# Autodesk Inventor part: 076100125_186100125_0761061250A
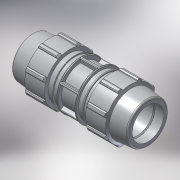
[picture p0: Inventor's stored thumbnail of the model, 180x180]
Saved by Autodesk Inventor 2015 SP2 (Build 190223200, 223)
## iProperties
Created: 2017-02
Part Number: 076100125_186100125_0761061250A
Material: PVC-Piping
Description: PLASSON REPAIR COUPLER 125
Document SubType Name: Modeling
Designer: KIM
Mass: 8658.36 g
Surface Area: 5623.3 cm^2
Volume: 6184.54 cm^3
Density: 1.4 g/cm^3
Appearance: Smooth - White
Author: KIM
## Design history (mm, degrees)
derived "07610.ipt"
feature "Solid1::07610.ipt"
tag "TaggingFeature1"
body "Solid1"
other parameters: "d2" = 125, "d4" = 38.33333, "d5" = 65.71429, "d7" = 212, "d8" = 159, "d9" = 65.71429, "d11" = 3.48571, "d12" = 169.6, "d13" = 120 deg, "d14" = 162.5, "d15" = 6 deg, "d16" = 190.8, "d18" = 6.25, "d19" = 35 deg, "d20" = 17.5 deg, "d21" = 197.16, "d23" = 0, "d25" = 360 deg, "d27" = 4.24, "d33" = 2.5, "d34" = 10.6, "d36" = 0, "d37" = 2.5, "d38" = 2.5, "d40" = 360 deg, "d42" = 82.8, "d43" = 6.36, "d46" = 3.75, "d50" = 19.28571, "d51" = 169.6, "d_" = 125, "E_" = 212, "l_" = 265, "d49" = 42.05714
